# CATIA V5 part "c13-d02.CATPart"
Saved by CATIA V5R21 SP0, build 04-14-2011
Part number: Part1
Bounding box of the stored display mesh (mm): x -33 to 33, y -200.819 to 48, z -35 to 35
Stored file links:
  D:\CATIA V5R21 E-RESOURCES\CATIA-V5R21\catia-v5r21-Prts\c13_catia_v5r21_prt\c13_catia_v5r21_figr_13-13\c13-d02.CATPart
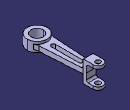
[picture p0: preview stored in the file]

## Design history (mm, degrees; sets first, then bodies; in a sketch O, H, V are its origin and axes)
Body1 (main body)
  Sketch1 on yz-plane, origin (0, 0, 0), H (0, 1, 0), V (0, 0, 1)
    line L1 (0, 0) -> (0, -35)
    point P1 (0, -35)
    line L2 (0, -35) -> (48, -35)
    point P2 (48, -35)
    line L3 (48, -35) -> (48, -25)
    point P3 (48, -25)
    line L4 (48, -25) -> (10, -25)
    point P4 (10, -25)
    line L5 (10, -25) -> (10, 0)
    point P5 (10, 0)
    point P6 (0, 0)
    point P7 (0, 0)
    point P8 (0, 35)
    point P9 (48, 35)
    point P10 (48, 25)
    point P11 (10, 25)
    point P12 (10, 0)
    point P13 (0, 0)
    line L6 (0, 0) -> (0, 35)
    line L7 (0, 35) -> (48, 35)
    line L8 (48, 35) -> (48, 25)
    line L9 (48, 25) -> (10, 25)
    line L10 (10, 25) -> (10, 0)
    length L8 = 10
    distance P3 L9 = 50
    length L2 = 48
    distance L10 L6 = 10
    vertical: L1 V, L3 V, L5 V
    horizontal: L2 H, L4 H
    symmetry: O P7 H, P1 P8 H, P2 P9 H, P3 P10 H, P4 P11 H, P5 P12 H, P6 P13 H, L1 L6 H, L2 L7 H, L3 L8 H, L4 L9 H, L5 L10 H
    coincidence: P13 P7, P12 P5, P6 P7
  Pad1: profile Sketch1, direction (1, 0, 0), length 16, mirrored extent
  Sketch2 on xy-plane, origin (0, 0, 0), H (1, 0, 0), V (0, 1, 0)
    circle A1 centre (0, -168) radius 33
    point P1 (0, -168)
    circle A2 centre (0, -168) radius 20
    distance P1 H = 168
    radius A1 = 33
    radius A2 = 20
    coincidence: P1 V
  Pad2: profile Sketch2, direction (0, 0, 1), length 16, mirrored extent
  Sketch3 on xy-plane, origin (0, 0, 0), H (1, 0, 0), V (0, 1, 0)
    line L1 (-16, 0) -> (-25, -146.4593)
    point P1 (-16, 0)
    point P2 (-25, -146.4593)
    line L2 (16, 0) -> (25, -146.4593)
    point P3 (16, 0)
    point P4 (25, -146.4593)
    reference projected line E1 (16, 48) -> (16, 0) from edge [face of Pad1 | face of Pad1]
    reference projected line E2 (-16, 48) -> (-16, 0) from edge [face of Pad1 | face of Pad1]
    projected circle E3 centre (0, -168) radius 33 from edge [face of Pad2 | face of Pad2]
    projected arc E4 centre (0, -168) radius 33 from (25, -146.4593) to (-25, -146.4593) ccw from edge [face of Pad2 | face of Pad2]
    line L3 (-16, 0) -> (16, 0)
    distance P4 P2 H = 50
    coincidence: P1 H, P3 H, P3 E1, P1 E2, P2 E3, P4 E3
    symmetry: P4 P2 V
    horizontal: L3 H
  Pad3: profile Sketch3, direction (0, 0, 1), length 8, mirrored extent
  Fillet1: radius 6, on edge [face of Pad1 | face of Pad3]; edge [face of Pad3 | face of Pad1]; edge [face of Pad1 | face of Pad1] (x2)
  Fillet2: radius 30, on edge [face of Pad3 | face of Pad2]; edge [face of Pad2 | face of Pad3]
  TritangentFillet1: Face1 face of Pad1, Face2 face of Pad1, RemoveFace face of Pad1
  TritangentFillet2: Face1 face of Pad1, Face2 face of Pad1, RemoveFace face of Pad1
  Sketch4 on face of Pad1, origin (2.8418, 32, 35), H (1, 0, 0), V (0, 1, 0)
    point P1 (-2.8418, 0)
    reference projected arc E1 centre (-2.8418, 0) radius 16 from (13.1582, 0) to (-18.8418, 0) ccw from edge [face of Pad1 | face of TritangentFillet1]
    concentricity: P1 E1
  Hole1: placed by Sketch4, at (0, 32, 35) direction (0, 0, -1), diameter 16, through (limit type 3)
  Sketch5 on face of Pad3, origin (0, 0, 8), H (1, 0, 0), V (0, 1, 0)
    construction line L1 (0, -25) -> (0, -115)
    point P1 (0, -25)
    line L2 (7, -25) -> (7, -115)
    line L3 (-7, -115) -> (-7, -25)
    arc A1 centre (0, -115) radius 7 from (7, -115) to (-7, -115) cw
    arc A2 centre (0, -25) radius 7 from (-7, -25) to (7, -25) cw
    distance P1 H = 25
    length L1 = 90
    radius A1 = 7
    coincidence: P1 V
    vertical: L1 V
    tangency: A1 L2, A2 L2, A1 L3, A2 L3
    parallelism: L1 L2
  Pocket1: profile Sketch5, direction (0, 0, -1), through (limit type 3)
